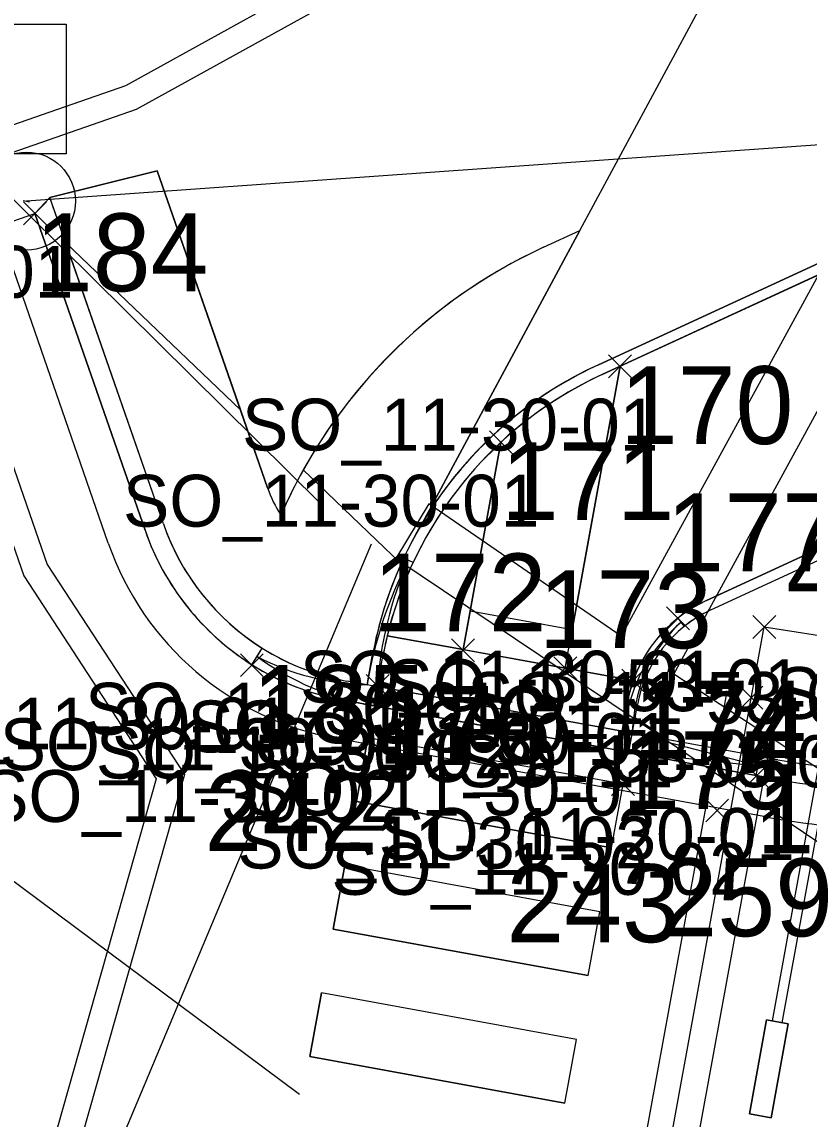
# Model space of a CAD drawing. Extents: x -728800 to -728100, y -1073200 to -1072700.
# Drawn here: x -728521.37 to -728515.29, y -1073056.81 to -1073048.35 of the extents above; entities that cross this region are included whole.
import ezdxf

# ---------------------------------------------------------------- set-up
doc = ezdxf.new("R2010")
doc.units = 0
for name, color, linetype in [('_NOR-návrh tenká', 7, 'Continuous'), ('_NOR-návrh tenká obec', 7, 'Continuous'), ('_NOR-VDZ', 7, 'Continuous'), ('_NOR-šraf_+-0', 7, 'Continuous'), ('_NOR-šraf_+12', 7, 'Continuous'), ('_NOR-šraf_+6', 7, 'Continuous'), ('_NOR-šraf_bezbariéra', 7, 'Continuous'), ('_NOR-šraf_chodník', 7, 'Continuous'), ('_NOR-šraf_signální pás', 7, 'Continuous'), ('_NOR-šraf_varovný pás', 7, 'Continuous'), ('_NOR-šraf_vozovka', 7, 'Continuous'), ('_NOR-šraf_zeleň', 7, 'Continuous'), ('A2_OBVOD STAVBY', 7, 'Continuous'), ('B1_body_poloha', 7, 'Continuous'), ('B2_body_číslo', 7, 'Continuous'), ('B3_body_popiska', 7, 'Continuous'), ('B4_Bodové pole', 7, 'Continuous'), ('B6_JŽM', 7, 'Continuous'), ('KOS_kabelová trasa VO', 7, 'Continuous'), ('KOS_nové prvky VO', 7, 'Continuous'), ('ZA_02_Dočasný_do_1_roku', 7, 'Continuous'), ('ZZZ_popisky', 7, 'Continuous')]:
    doc.layers.add(name, color=color, linetype=linetype)

msp = doc.modelspace()

# ---------------------------------------------------------------- linework, layer by layer
at = {"layer": '_NOR-návrh tenká'}
for p, q in [((-728517.1763, -1073053.3333), (-728516.7519, -1073051.0049)), ((-728517.9633, -1073053.1899), (-728517.672, -1073051.5916)), ((-728518.3497, -1073052.5187), (-728518.4221, -1073052.4847)), ((-728516.3067, -1073052.9482), (-728516.2569, -1073053.0107)), ((-728519.5924, -1073053.3065), (-728519.5126, -1073053.1795)), ((-728516.7364, -1073053.8201), (-728516.6877, -1073053.6309)), ((-728516.6577, -1073053.8344), (-728516.6366, -1073053.6402)), ((-728515.6874, -1073054.0875), (-728516.6577, -1073053.8344)), ((-728516.6846, -1073053.982), (-728515.6874, -1073054.0875))]:
    msp.add_line(p, q, dxfattribs=at)
for points in [[(-728516.9231, -1073050.9957), (-728512.437, -1073048.9275)], [(-728516.8896, -1073051.0683), (-728512.3565, -1073048.9785)], [(-728519.4728, -1073051.9415), (-728520.3228, -1073049.4978), (-728521.1508, -1073049.7044)], [(-728520.2757, -1073052.2207), (-728521.1508, -1073049.7044), (-728521.2673, -1073049.8263)], [(-728520.7007, -1073052.3686), (-728521.5506, -1073049.9248), (-728521.2673, -1073049.8263)], [(-728520.4173, -1073052.27), (-728521.2673, -1073049.8263)], [(-728517.3418, -1073050.0876), (-728517.0623, -1073049.9587)], [(-728516.0858, -1073052.812), (-728510.6464, -1073050.3043)], [(-728516.0523, -1073052.8846), (-728510.6571, -1073050.3973)], [(-728516.6506, -1073053.4291), (-728518.5485, -1073053.0832)], [(-728518.704, -1073053.4615), (-728518.6637, -1073053.2406)], [(-728518.6522, -1073053.6234), (-728518.585, -1073053.2549)], [(-728515.5346, -1073054.0391), (-728518.86, -1073053.4331)], [(-728515.5615, -1073054.1867), (-728518.8869, -1073053.5806)], [(-728516.7364, -1073053.8201), (-728516.6961, -1073053.5991)], [(-728516.6846, -1073053.982), (-728516.6174, -1073053.6135)], [(-728515.6153, -1073054.4818), (-728518.9407, -1073053.8758)], [(-728515.7008, -1073054.1613), (-728515.6739, -1073054.0137)]]:
    msp.add_lwpolyline(points, dxfattribs=at)
for centre, radius, start, end in [((-728515.6336, -1073053.7928), 4.08, 114.75046, 156.30852), ((-728515.6336, -1073053.7928), 3.08, 114.75046, 169.67159), ((-728515.6336, -1073053.7928), 3, 114.75046, 169.67159), ((-728518.5283, -1073051.613), 1, 199.17748, 212.70637), ((-728518.5283, -1073051.613), 2, 199.17748, 259.67159), ((-728518.5283, -1073051.613), 1.85, 199.17645, 259.67159), ((-728518.5283, -1073051.613), 2.3, 199.17748, 259.67159), ((-728515.4086, -1073054.0212), 3.3426, 152.96231, 170.36142), ((-728515.6969, -1073053.6791), 2.9355, 156.35328, 176.02944), ((-728515.6336, -1073053.7928), 1.08, 114.75046, 169.67159), ((-728515.6336, -1073053.7928), 1, 114.75046, 169.67159), ((-728515.4667, -1073053.9394), 1.2593, 130.33267, 165.81674), ((-728515.524, -1073053.8119), 1.1258, 132.31031, 171.22351), ((-728518.2959, -1073051.5247), 2.1288, 233.82126, 260.36512), ((-728518.6629, -1073051.5451), 1.9168, 242.34554, 268.77004), ((-728514.4858, -1073048.2839), 5.85, 259.67159, 279.85546), ((-728514.4858, -1073048.2839), 6, 259.67159, 279.85546), ((-728514.4858, -1073048.2839), 6.3, 259.67159, 279.85546)]:
    msp.add_arc(centre, radius, start, end, dxfattribs=at)
at = {"layer": '_NOR-návrh tenká obec'}
for p, q in [((-728518.7867, -1073054.3613), (-728518.697, -1073053.8694)), ((-728516.7294, -1073054.2279), (-728518.697, -1073053.8694)), ((-728516.8191, -1073054.7198), (-728516.7294, -1073054.2279)), ((-728516.8191, -1073054.7198), (-728518.7867, -1073054.3613)), ((-728518.9659, -1073055.3451), (-728518.8763, -1073054.8532)), ((-728516.9087, -1073055.2117), (-728518.8763, -1073054.8532)), ((-728516.9984, -1073055.7036), (-728516.9087, -1073055.2117)), ((-728516.9984, -1073055.7036), (-728518.9659, -1073055.3451)), ((-728519.1452, -1073056.3288), (-728519.0556, -1073055.837)), ((-728517.088, -1073056.1955), (-728519.0556, -1073055.837)), ((-728517.1776, -1073056.6874), (-728517.088, -1073056.1955)), ((-728517.1776, -1073056.6874), (-728519.1452, -1073056.3288))]:
    msp.add_line(p, q, dxfattribs=at)
at = {"layer": '_NOR-VDZ'}
for p, q in [((-728518.7867, -1073054.3613), (-728518.697, -1073053.8694)), ((-728516.7294, -1073054.2279), (-728518.697, -1073053.8694)), ((-728516.8191, -1073054.7198), (-728516.7294, -1073054.2279)), ((-728516.8191, -1073054.7198), (-728518.7867, -1073054.3613)), ((-728518.9659, -1073055.3451), (-728518.8763, -1073054.8532)), ((-728516.9087, -1073055.2117), (-728518.8763, -1073054.8532)), ((-728516.9984, -1073055.7036), (-728516.9087, -1073055.2117)), ((-728516.9984, -1073055.7036), (-728518.9659, -1073055.3451)), ((-728519.1452, -1073056.3288), (-728519.0556, -1073055.837)), ((-728517.088, -1073056.1955), (-728519.0556, -1073055.837)), ((-728517.1776, -1073056.6874), (-728517.088, -1073056.1955)), ((-728517.1776, -1073056.6874), (-728519.1452, -1073056.3288))]:
    msp.add_line(p, q, dxfattribs=at)
for points in [[(-728516.8191, -1073054.7198), (-728516.7294, -1073054.2279), (-728518.697, -1073053.8694), (-728518.7867, -1073054.3613), (-728516.8191, -1073054.7198)], [(-728516.9984, -1073055.7036), (-728516.9087, -1073055.2117), (-728518.8763, -1073054.8532), (-728518.9659, -1073055.3451), (-728516.9984, -1073055.7036)], [(-728517.1776, -1073056.6874), (-728517.088, -1073056.1955), (-728519.0556, -1073055.837), (-728519.1452, -1073056.3288), (-728517.1776, -1073056.6874)]]:
    msp.add_lwpolyline(points, dxfattribs=at)
at = {"layer": '_NOR-šraf_+-0'}
for points in [[(-728516.0523, -1073052.8846), (-728510.6571, -1073050.3973), (-728510.6464, -1073050.3043), (-728516.0858, -1073052.812)], [(-728516.3067, -1073052.9482), (-728516.2818, -1073052.9794)], [(-728516.2818, -1073052.9794), (-728516.2569, -1073053.0107)]]:
    msp.add_lwpolyline(points, dxfattribs=at)
for radius in [1.08, 1]:
    msp.add_arc((-728515.6336, -1073053.7928), radius, 114.75046, 128.55144, dxfattribs=at)
at = {"layer": '_NOR-šraf_+12'}
for points in [[(-728520.2757, -1073052.2207), (-728521.1508, -1073049.7044), (-728521.2673, -1073049.8263)], [(-728521.2673, -1073049.8263), (-728520.4173, -1073052.27)], [(-728519.5924, -1073053.3065), (-728519.5525, -1073053.243), (-728519.5126, -1073053.1795)], [(-728515.7008, -1073054.1613), (-728515.6874, -1073054.0875), (-728515.6739, -1073054.0137), (-728515.5346, -1073054.0391)], [(-728515.5615, -1073054.1867), (-728515.7008, -1073054.1613)]]:
    msp.add_lwpolyline(points, dxfattribs=at)
for centre, radius, start, end in [((-728518.5283, -1073051.613), 2, 199.17748, 237.85612), ((-728518.5283, -1073051.613), 1.85, 199.17645, 237.85612), ((-728514.4858, -1073048.2839), 5.85, 259.67159, 279.85546), ((-728514.4858, -1073048.2839), 6, 259.67159, 279.85546)]:
    msp.add_arc(centre, radius, start, end, dxfattribs=at)
at = {"layer": '_NOR-šraf_+6'}
for points in [[(-728516.9231, -1073050.9957), (-728512.437, -1073048.9275), (-728512.4624, -1073046.6351)], [(-728512.4624, -1073046.6351), (-728512.3823, -1073046.6472), (-728512.3823, -1073046.6472), (-728512.3778, -1073047.0523), (-728512.3598, -1073048.6815), (-728512.3565, -1073048.9785), (-728516.7519, -1073051.0049), (-728516.8896, -1073051.0683)], [(-728518.3497, -1073052.5187), (-728518.4221, -1073052.4847)]]:
    msp.add_lwpolyline(points, dxfattribs=at)
for radius, start, end in [(3.08, 114.75046, 154.86884), (3, 114.75046, 132.8017), (3, 132.8017, 154.86884)]:
    msp.add_arc((-728515.6336, -1073053.7928), radius, start, end, dxfattribs=at)
at = {"layer": '_NOR-šraf_bezbariéra'}
msp.add_lwpolyline([(-728516.6846, -1073053.982), (-728516.6577, -1073053.8344), (-728518.6253, -1073053.4758), (-728518.6522, -1073053.6234), (-728516.6846, -1073053.982), (-728516.6846, -1073053.982)], dxfattribs=at)
at = {"layer": '_NOR-šraf_chodník'}
for p, q in [((-728516.7519, -1073051.0049), (-728512.3565, -1073048.9785)), ((-728510.6464, -1073050.3043), (-728516.0858, -1073052.812)), ((-728517.1763, -1073053.3333), (-728516.7519, -1073051.0049)), ((-728517.672, -1073051.5916), (-728517.9633, -1073053.1899)), ((-728517.9633, -1073053.1899), (-728518.5485, -1073053.0832)), ((-728516.6506, -1073053.4291), (-728517.1763, -1073053.3333))]:
    msp.add_line(p, q, dxfattribs=at)
for radius, start, end in [(3, 132.8017, 154.86884), (3, 154.86884, 166.31949), (1.08, 114.75046, 128.55144), (1.08, 128.55144, 160.3241)]:
    msp.add_arc((-728515.6336, -1073053.7928), radius, start, end, dxfattribs=at)
at = {"layer": '_NOR-šraf_signální pás'}
for p, q in [((-728516.7519, -1073051.0049), (-728517.1225, -1073053.0382)), ((-728516.8896, -1073051.0683), (-728516.7519, -1073051.0049)), ((-728517.9095, -1073052.8948), (-728517.672, -1073051.5916)), ((-728517.1225, -1073053.0382), (-728517.9095, -1073052.8948))]:
    msp.add_line(p, q, dxfattribs=at)
msp.add_lwpolyline([(-728517.1763, -1073053.3333), (-728517.1225, -1073053.0382), (-728517.9095, -1073052.8948), (-728517.9633, -1073053.1899), (-728517.1763, -1073053.3333)], dxfattribs=at)
msp.add_arc((-728515.6336, -1073053.7928), 3, 114.75046, 132.8017, dxfattribs=at)
at = {"layer": '_NOR-šraf_varovný pás'}
for points in [[(-728518.5485, -1073053.0832), (-728517.9633, -1073053.1899), (-728517.1763, -1073053.3333), (-728516.6506, -1073053.4291)], [(-728518.6253, -1073053.4758), (-728518.585, -1073053.2549)], [(-728516.6961, -1073053.5991), (-728516.7364, -1073053.8201), (-728518.6253, -1073053.4758), (-728518.6253, -1073053.4758)]]:
    msp.add_lwpolyline(points, dxfattribs=at)
for radius, start in [(3, 166.31949), (1.08, 160.3241)]:
    msp.add_arc((-728515.6336, -1073053.7928), radius, start, 169.67159, dxfattribs=at)
at = {"layer": '_NOR-šraf_vozovka'}
for points in [[(-728521.5506, -1073049.9248), (-728521.2673, -1073049.8263), (-728520.4173, -1073052.27)], [(-728520.7007, -1073052.3686), (-728521.5506, -1073049.9248)], [(-728518.8869, -1073053.5806), (-728518.7029, -1073053.6142)], [(-728518.6522, -1073053.6234), (-728518.6522, -1073053.6234), (-728516.6846, -1073053.982), (-728516.6846, -1073053.982), (-728515.7008, -1073054.1613), (-728515.5615, -1073054.1867)], [(-728515.6153, -1073054.4818), (-728518.9407, -1073053.8758)]]:
    msp.add_lwpolyline(points, dxfattribs=at)
for centre, radius, start, end in [((-728518.5283, -1073051.613), 2, 199.17748, 237.85612), ((-728518.5283, -1073051.613), 2.3, 199.17748, 259.67159), ((-728518.5283, -1073051.613), 2, 237.85612, 259.67159), ((-728518.2959, -1073051.5247), 2.1288, 258.97807, 260.36512), ((-728514.4858, -1073048.2839), 6, 259.67159, 279.85546), ((-728514.4858, -1073048.2839), 6.3, 259.67159, 279.85546)]:
    msp.add_arc(centre, radius, start, end, dxfattribs=at)
at = {"layer": '_NOR-šraf_zeleň'}
for p, q in [((-728520.2757, -1073052.2207), (-728521.0294, -1073050.0536)), ((-728519.1966, -1073051.8048), (-728518.445, -1073052.523)), ((-728518.445, -1073052.523), (-728519.1966, -1073051.8048)), ((-728518.4046, -1073052.4481), (-728518.445, -1073052.523)), ((-728518.445, -1073052.523), (-728518.4409, -1073052.5257)), ((-728518.6637, -1073053.2406), (-728518.6896, -1073053.3823)), ((-728518.704, -1073053.4615), (-728518.86, -1073053.4331)), ((-728516.6362, -1073053.7163), (-728516.6174, -1073053.6135)), ((-728516.6577, -1073053.8344), (-728516.6362, -1073053.7163)), ((-728516.6362, -1073053.7163), (-728516.3807, -1073053.8849)), ((-728516.3807, -1073053.8849), (-728516.6362, -1073053.7163)), ((-728516.3807, -1073053.8849), (-728516.6577, -1073053.8344)), ((-728515.5346, -1073054.0391), (-728516.3807, -1073053.8849))]:
    msp.add_line(p, q, dxfattribs=at)
for points in [[(-728518.2797, -1073052.2165), (-728517.0623, -1073049.9587), (-728515.0597, -1073046.2449)], [(-728515.0597, -1073046.2449), (-728512.4624, -1073046.6351), (-728512.437, -1073048.9275), (-728516.9231, -1073050.9957)], [(-728521.1508, -1073049.7044), (-728520.3228, -1073049.4978), (-728519.6815, -1073051.3415), (-728521.0294, -1073050.0536), (-728521.1508, -1073049.7044)], [(-728517.3418, -1073050.0876), (-728517.0623, -1073049.9587), (-728518.2797, -1073052.2165)], [(-728521.0294, -1073050.0536), (-728519.6815, -1073051.3415), (-728519.4728, -1073051.9415)], [(-728516.0523, -1073052.8846), (-728510.6571, -1073050.3973), (-728510.7036, -1073050.8035), (-728510.5546, -1073050.8206), (-728510.651, -1073051.661), (-728511.32, -1073052.432), (-728511.438, -1073052.141), (-728512.732, -1073052.372), (-728512.6386, -1073053.0791), (-728512.7873, -1073053.0987)]]:
    msp.add_lwpolyline(points, dxfattribs=at)
for centre, radius, start, end in [((-728515.6336, -1073053.7928), 4.08, 114.75046, 150.84105), ((-728515.6336, -1073053.7928), 3.08, 114.75046, 149.21786), ((-728515.6336, -1073053.7928), 4.08, 150.84105, 156.30852), ((-728518.5283, -1073051.613), 1, 199.17748, 212.70637), ((-728518.5283, -1073051.613), 1.85, 199.17645, 237.85612), ((-728515.6336, -1073053.7928), 3.08, 149.21786, 154.11354), ((-728515.6336, -1073053.7928), 3.08, 155.70778, 169.67159), ((-728515.6336, -1073053.7928), 1, 114.75046, 169.67159), ((-728518.5283, -1073051.613), 1.85, 237.85612, 252.32749), ((-728518.5283, -1073051.613), 1.85, 252.32749, 259.67159), ((-728515.4086, -1073054.0212), 3.3426, 168.98177, 170.36142), ((-728514.4858, -1073048.2839), 5.85, 259.67159, 279.85546)]:
    msp.add_arc(centre, radius, start, end, dxfattribs=at)
at = {"layer": 'A2_OBVOD STAVBY'}
msp.add_lwpolyline([(-728517.2093, -1073045.1291), (-728517.5964, -1073047.2005), (-728520.5688, -1073048.8422), (-728522.4417, -1073049.4936), (-728521.3538, -1073052.6217), (-728520.3306, -1073054.1859), (-728521.7354, -1073059.131)], dxfattribs=at)
at = {"layer": 'B1_body_poloha'}
for p, q in [((-728521.3554, -1073049.7386), (-728521.1786, -1073049.9154)), ((-728521.3554, -1073049.9154), (-728521.1786, -1073049.7386)), ((-728516.8414, -1073050.9166), (-728516.6646, -1073051.0934)), ((-728516.8414, -1073051.0934), (-728516.6646, -1073050.9166)), ((-728517.7594, -1073051.5036), (-728517.5826, -1073051.6804)), ((-728517.7594, -1073051.6804), (-728517.5826, -1073051.5036)), ((-728516.3944, -1073052.8606), (-728516.2176, -1073053.0374)), ((-728516.3944, -1073053.0374), (-728516.2176, -1073052.8606)), ((-728515.7278, -1073052.927), (-728515.551, -1073053.1038)), ((-728515.7278, -1073053.1038), (-728515.551, -1073052.927)), ((-728518.0524, -1073053.1076), (-728517.8756, -1073053.2844)), ((-728518.0524, -1073053.2844), (-728517.8756, -1073053.1076)), ((-728519.6814, -1073053.2216), (-728519.5046, -1073053.3984)), ((-728519.6814, -1073053.3984), (-728519.5046, -1073053.2216)), ((-728517.2624, -1073053.2446), (-728517.0856, -1073053.4214)), ((-728517.2624, -1073053.4214), (-728517.0856, -1073053.2446)), ((-728518.7104, -1073053.3816), (-728518.5336, -1073053.5584)), ((-728518.7104, -1073053.5584), (-728518.5336, -1073053.3816)), ((-728516.7394, -1073053.3416), (-728516.5626, -1073053.5184)), ((-728516.7394, -1073053.5184), (-728516.5626, -1073053.3416)), ((-728515.8274, -1073053.4726), (-728515.6506, -1073053.6494)), ((-728515.8274, -1073053.6494), (-728515.6506, -1073053.4726)), ((-728518.7854, -1073053.7806), (-728518.6086, -1073053.9574)), ((-728518.7854, -1073053.9574), (-728518.6086, -1073053.7806)), ((-728516.8178, -1073054.1396), (-728516.641, -1073054.3163)), ((-728516.8178, -1073054.3163), (-728516.641, -1073054.1396)), ((-728515.7874, -1073054.0736), (-728515.6106, -1073054.2504)), ((-728515.7874, -1073054.2504), (-728515.6106, -1073054.0736)), ((-728516.0914, -1073054.3426), (-728515.9146, -1073054.5194)), ((-728516.0914, -1073054.5194), (-728515.9146, -1073054.3426))]:
    msp.add_line(p, q, dxfattribs=at)
at = {"layer": 'B2_body_číslo'}
for p, q in [((-728521.267, -1073049.827), (-728521.267, -1073049.827)), ((-728516.753, -1073051.005), (-728516.753, -1073051.005)), ((-728517.671, -1073051.592), (-728517.671, -1073051.592)), ((-728516.306, -1073052.949), (-728516.306, -1073052.949)), ((-728515.639, -1073053.015), (-728515.639, -1073053.015)), ((-728517.964, -1073053.196), (-728517.964, -1073053.196)), ((-728519.593, -1073053.31), (-728519.593, -1073053.31)), ((-728517.174, -1073053.333), (-728517.174, -1073053.333)), ((-728518.622, -1073053.47), (-728518.622, -1073053.47)), ((-728516.651, -1073053.43), (-728516.651, -1073053.43)), ((-728517.82, -1073053.534), (-728517.82, -1073053.534)), ((-728515.739, -1073053.561), (-728515.739, -1073053.561)), ((-728518.697, -1073053.869), (-728518.697, -1073053.869)), ((-728516.736, -1073053.82), (-728516.736, -1073053.82)), ((-728516.729, -1073054.228), (-728516.729, -1073054.228)), ((-728515.699, -1073054.162), (-728515.699, -1073054.162)), ((-728516.003, -1073054.431), (-728516.003, -1073054.431)), ((-728515.622, -1073056.045), (-728515.622, -1073056.045)), ((-728515.455, -1073056.075), (-728515.455, -1073056.075)), ((-728515.754, -1073056.769), (-728515.754, -1073056.769)), ((-728515.587, -1073056.799), (-728515.587, -1073056.799))]:
    msp.add_line(p, q, dxfattribs=at)
at = {"layer": 'B4_Bodové pole'}
for p, q in [((-728502.086, -1073048.369), (-728521.333, -1073049.732)), ((-728521.3575, -1073049.727), (-728521.3085, -1073049.737))]:
    msp.add_line(p, q, dxfattribs=at)
msp.add_circle((-728521.333, -1073049.732), 0.378, dxfattribs=at)
at = {"layer": 'B6_JŽM'}
msp.add_line((-728522.31, -1073061.049), (-728518.67, -1073052.375), dxfattribs=at)
for points in [[(-728519.061, -1073052.066), (-728523.329, -1073047.846), (-728527.39, -1073043.448), (-728532.404, -1073042.69)], [(-728515.148, -1073054.725), (-728514.9, -1073054.321), (-728516.336, -1073053.379), (-728512.168, -1073045.742), (-728510.38, -1073046.047), (-728509.916, -1073045.565), (-728514.343, -1073044.959), (-728514.586, -1073045.376), (-728512.695, -1073045.676), (-728516.744, -1073053.086), (-728518.227, -1073052.067), (-728518.483, -1073052.487), (-728515.148, -1073054.725)], [(-728522.025, -1073048.368), (-728521.025, -1073048.368), (-728521.025, -1073049.368), (-728522.025, -1073049.368), (-728522.025, -1073048.368)]]:
    msp.add_lwpolyline(points, dxfattribs=at)
at = {"layer": 'KOS_kabelová trasa VO'}
for p, q in [((-728515.9316, -1073053.5256), (-728517.4088, -1073061.6125)), ((-728515.5381, -1073053.5975), (-728517.0153, -1073061.6844))]:
    msp.add_line(p, q, dxfattribs=at)
msp.add_lwpolyline([(-728528.7388, -1073080.1922), (-728527.3958, -1073080.5542), (-728522.1845, -1073062.5559), (-728521.7095, -1073061.3747), (-728517.3063, -1073062.1713), (-728515.6394, -1073053.0154), (-728515.0161, -1073053.1134), (-728515.0904, -1073053.6006)], dxfattribs=at)
at = {"layer": 'KOS_nové prvky VO'}
for p, q in [((-728515.576, -1073056.0533), (-728515.1376, -1073053.6475)), ((-728515.5012, -1073056.0669), (-728515.0628, -1073053.6611))]:
    msp.add_line(p, q, dxfattribs=at)
msp.add_lwpolyline([(-728515.7542, -1073056.769), (-728515.6222, -1073056.0449), (-728515.455, -1073056.0754), (-728515.587, -1073056.7995)], close=True, dxfattribs=at)
msp.add_lwpolyline([(-728515.587, -1073056.7995), (-728515.455, -1073056.0754), (-728515.6222, -1073056.0449), (-728515.7542, -1073056.769), (-728515.587, -1073056.7995)], dxfattribs=at)
at = {"layer": 'ZA_02_Dočasný_do_1_roku'}
msp.add_lwpolyline([(-728515.2033, -1073056.8181), (-728511.1894, -1073055.1227), (-728508.5954, -1073049.5354), (-728508.4924, -1073048.6368), (-728517.3822, -1073047.3107), (-728520.487, -1073049.0255), (-728522.1871, -1073049.6168), (-728521.173, -1073052.5328), (-728520.1133, -1073054.1527), (-728521.5861, -1073059.3376)], dxfattribs=at)
at = {"layer": 'ZZZ_popisky'}
msp.add_lwpolyline([(-728519.225, -1073056.6197), (-728526.0321, -1073051.5541), (-728527.991, -1073054.1865)], dxfattribs=at)

# ---------------------------------------------------------------- texts
at = {"layer": 'B2_body_číslo'}
for s, p in [('184', (-728521.267, -1073050.427)), ('170', (-728516.753, -1073051.605)), ('171', (-728517.671, -1073052.192)), ('177', (-728516.3946, -1073052.5864)), ('437', (-728515.4692, -1073052.8761)), ('172', (-728518.6582, -1073053.0497)), ('173', (-728517.3808, -1073053.179)), ('185', (-728519.593, -1073053.91)), ('176', (-728518.622, -1073054.07)), ('174', (-728516.651, -1073054.03)), ('449', (-728515.739, -1073054.161)), ('175', (-728516.736, -1073054.42)), ('242', (-728519.9598, -1073054.7435)), ('186', (-728515.699, -1073054.762)), ('259', (-728516.4475, -1073055.4004)), ('243', (-728517.6299, -1073055.4461))]:
    msp.add_text(s, height=0.6, dxfattribs=at).set_placement(p)
at = {"layer": 'B3_body_popiska'}
for s, p in [('SO_11-30-01', (-728524.1829, -1073050.477)), ('SO_11-30-01', (-728519.6689, -1073051.655)), ('SO_11-30-01', (-728520.5869, -1073052.242)), ('SO_11-30-01', (-728519.2219, -1073053.599)), ('SO_11-53-01', (-728518.5549, -1073053.665)), ('SO_11-53-01', (-728517.9319, -1073053.763)), ('SO_11-30-01', (-728515.5539, -1073053.725)), ('SO_11-30-01', (-728520.8799, -1073053.846)), ('SO_11-30-01', (-728522.5089, -1073053.96)), ('SO_11-30-01', (-728520.0899, -1073053.983)), ('SO_11-30-01', (-728521.5379, -1073054.12)), ('SO_11-30-01', (-728519.5669, -1073054.08)), ('SO_11-30-02', (-728520.7965, -1073054.184)), ('SO_11-53-01', (-728518.6549, -1073054.211)), ('SO_11-53-01', (-728518.0059, -1073054.251)), ('SO_11-30-01', (-728519.6519, -1073054.47)), ('SO_11-30-02', (-728521.6735, -1073054.519)), ('SO_11-30-01', (-728518.6149, -1073054.812)), ('SO_11-30-02', (-728519.7055, -1073054.878)), ('SO_11-30-02', (-728518.9795, -1073055.081))]:
    msp.add_text(s, height=0.4, dxfattribs=at).set_placement(p)

doc.saveas('drawing.dxf')
